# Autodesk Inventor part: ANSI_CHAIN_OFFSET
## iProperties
Author: Ole Germer
Shininess: 64.0
Angle Display Precision: 2
Document Length Units: 11272
Document Angle Units: 11286
Document Time Units: 11279
Document Mass Units: 11290
Document Length Units Precision: 3
Document Angle Units Precision: 2
Compacted: True
PropertySet Name: _Private Model Information
Created: 2002-08
Part Number: ANSI_CHAIN_OFFSET
Material: ASTM A36 HRS
Document SubType Name: Modeling
Designer: Ole Germer
Control State: 0
Master: False
Checked Out: False
PropertySet Name: Design Tracking Control
Density: 0.0
Volumn: 0.0
Area: 0.0
PropertySet Name: Model Information
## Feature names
1. side_plate [Extrusion]
2. bend_cutout [Extrusion]
3. Fillet1
4. 2nd_side_plate [Mirror]
5. pin [Extrusion]
6. bushing [Extrusion]
7. Rectangular Pattern1
